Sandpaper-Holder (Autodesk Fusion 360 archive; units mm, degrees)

design "Sandpaper-Holder" references "Base"
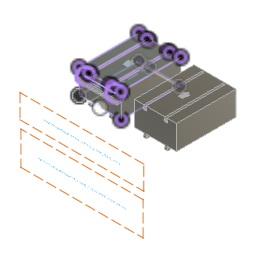
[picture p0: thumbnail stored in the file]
parameter "width" = 110
parameter "depth" = 160
parameter "height" = 50
parameter "wall_thickness" = 2
sketch "Sketch1" plane through (0, 0, 0) normal (0, 1, 0) x axis (1, 0, 0)
  line L1 (110, 0) -> (0, 0)
  line L2 (0, -50) -> (0, 0)
  line L3 (110, -50) -> (0, -50)
  line L4 (110, 0) -> (110, -50)
  line L5 (112, 2) -> (-2, 2)
  line L6 (112, 2) -> (112, -52)
  line L7 (112, -52) -> (-2, -52)
  line L8 (-2, -52) -> (-2, 2)
  point P1 (0, 0)
  point P2 (0, 0)
  point P4 (0, 0)
  point P3 (110, 0)
  point P5 (0, -50)
  coincident P1 P2
  horizontal L1
  coincident P1 P4
  perpendicular L1 L2
  perpendicular L2 L3
  perpendicular L1 L4
  dimension "d6" distance P2 P3 = 110 (= "width")
  dimension "d7" distance P4 P5 = 50 (= "height")
  dimension "d8" = 2 (= "wall_thickness")
extrude "Extrude1" new body sketch "Sketch1" along normal blind 160 (= "depth") bodies "Box"
sketch "Sketch2" plane through (0, 160, 0) normal (0, 1, 0) x axis (-1, 0, 0)
  line L1 (0, 0) -> (0, 50)
  line L2 (-110, 0) -> (0, 0)
  line L3 (-110, 50) -> (-110, 0)
  line L4 (0, 50) -> (-110, 50)
  line L5 (2, 52) -> (2, -2)
  line L6 (-112, 52) -> (2, 52)
  line L7 (-112, -2) -> (-112, 52)
  line L8 (2, -2) -> (-112, -2)
  line L9 (2, 52) -> (2, -2)
  line L10 (-112, 52) -> (2, 52)
  line L11 (-112, -2) -> (-112, 52)
  line L12 (2, -2) -> (-112, -2)
  line L13 (2, 52) -> (-112, 52)
  line L14 (2, -2) -> (2, 52)
  line L15 (-112, -2) -> (2, -2)
  line L16 (-112, 52) -> (-112, -2)
  point P6 (2, -2)
  point P16 (2, -2)
  point P8 (-112, 52)
  point P14 (-112, 52)
  horizontal L13
  vertical L14
  horizontal L15
  vertical L16
  coincident P6 P16
  coincident P8 P14
extrude "Extrude2" add sketch "Sketch2" along normal blind 2 (= "wall_thickness")
fillet "Fillet1" radius 1 (= "wall_thickness / 2")
component_insert "Component Insert"
sketch "Sketch3" plane through (0, 55.6118, 0) normal (0, 1, 0) x axis (-1, 0, 0)
  line L1 (0, 52.6059) -> (-80, 52.6059)
  line L2 (0, 60) -> (0, 52.6059)
  line L3 (-80, 60) -> (0, 60)
  line L4 (-80, 52.6059) -> (-80, 60)
  line L5 (-80, 60) -> (0, 60)
move "Move1"
move "Move2"
extrude "Extrude3" new body of existing geometry blind 410
extrude "Extrude4" new body of existing geometry blind 97 bodies "Slider Back"
remove_body "RemoveBody1"
extrude "Extrude6" add of existing geometry to an object
sketch "Sketch4" plane through (0, 0, 6) normal (0, 0, -1) x axis (1, 0, 0)
  line L1 (97, -217.6118) -> (-17, -217.6118)
  line L2 (97, -55.6118) -> (97, -217.6118)
  line L3 (-17, -55.6118) -> (97, -55.6118)
  line L4 (-17, -217.6118) -> (-17, -55.6118)
  line L5 (40, -55.6118) -> (-17, -55.6118)
  line L6 (40, -217.6118) -> (39.5082, -55.6118)
  line L7 (11.5, -217.6118) -> (11.5, -55.6118)
  line L8 (-17, -212.6118) -> (-17, -217.6118)
  line L9 (97, -212.6118) -> (-17, -212.6118)
  point P5 (-17, -55.6118)
  point P6 (-17, -55.6118)
  point P8 (39.5082, -55.6118)
  point P9 (40, -217.6118)
  point P10 (11.5, -55.6118)
  point P11 (11.5, -217.6118)
  point P2 (-17, -217.6118)
  point P12 (-17, -217.6118)
  point P14 (97, -212.6118)
  point P7 (40, -55.6118)
  point P13 (-17, -212.6118)
  coincident P5 P6
  perpendicular L4 L5
  coincident L5 P8
  midpoint L1 P9
  midpoint L5 P10
  coincident L1 P11
  perpendicular L1 L7
  coincident P2 P12
  perpendicular L1 L8
  coincident L2 P14
  perpendicular L2 L9
  dimension "d23" distance P6 P7 = 57 (= "( wall_thickness + wall_thickness + width ) / 2")
  dimension "d24" distance P12 P13 = 5
copy_paste_bodies "CopyPasteBodies1"
move "Move3"
move "Move4"
extrude "Extrude7" add of existing geometry to an object
work_plane "WorkPlane1" AlongDistance -57 (= "-( wall_thickness + wall_thickness + width ) / 2")
mirror "Mirror1" mirrorStitchTolerance 0.1 bodies "Slider (1) (1)"
extrude "Extrude8" add of existing geometry blind 12
sketch "Sketch5" plane through (160, 0, 0) normal (1, 0, 0) x axis (0, 1, 0)
  line L1 (44.6118, 54.0559) -> (44.6118, 50.6559)
  line L2 (49.1118, 54.0559) -> (44.6118, 54.0559)
  line L3 (49.1118, 52.6059) -> (49.1118, 54.0559)
  line L4 (55.6118, 52.6059) -> (49.1118, 52.6059)
  line L5 (55.6118, 60) -> (55.6118, 52.6059)
  line L6 (39.6118, 60) -> (55.6118, 60)
  line L7 (39.6118, -40) -> (39.6118, 60)
  line L8 (55.6118, -40) -> (39.6118, -40)
  line L9 (55.6118, 47.0059) -> (55.6118, -40)
  line L10 (49.1118, 47.0059) -> (55.6118, 47.0059)
  line L11 (49.1118, 45.5559) -> (49.1118, 47.0059)
  line L12 (44.6118, 45.5559) -> (49.1118, 45.5559)
  line L13 (44.6118, 48.9559) -> (44.6118, 45.5559)
  line L14 (44.6118, 54.0559) -> (44.6118, 50.6559)
  line L15 (49.1118, 54.0559) -> (44.6118, 54.0559)
  line L16 (49.1118, 52.6059) -> (49.1118, 54.0559)
  line L17 (55.6118, 52.6059) -> (49.1118, 52.6059)
  line L18 (44.6118, 48.9559) -> (44.6118, 45.5559)
  line L19 (44.6118, 45.5559) -> (49.1118, 45.5559)
  line L20 (49.1118, 45.5559) -> (49.1118, 47.0059)
  line L21 (49.1118, 47.0059) -> (55.6118, 47.0059)
  line L22 (55.6118, 47.0059) -> (55.6118, 52.6059)
  arc A1 centre (44.6118, 49.8059) radius 0.85 clockwise from (44.6118, 48.9559) to (44.6118, 50.6559)
  arc A2 centre (44.6118, 49.8059) radius 0.85 clockwise from (44.6118, 48.9559) to (44.6118, 50.6559)
  point P24 (55.6118, 52.6059)
  point P36 (55.6118, 52.6059)
  point P34 (55.6118, 47.0059)
  point P37 (55.6118, 47.0059)
  coincident P24 P36
  coincident P34 P37
sketch "Sketch6" plane through (0, 0, 72) normal (0, 0, 1) x axis (-1, 0, 0)
  line L1 (17, -217.6118) -> (-97, -217.6118)
  line L2 (17, -55.6118) -> (17, -217.6118)
  line L3 (-97, -55.6118) -> (17, -55.6118)
  line L4 (-97, -217.6118) -> (-97, -55.6118)
  line L5 (-11.5, -217.6118) -> (-11.5, -55.6118)
extrude "Extrude9" new body sketch "Sketch5" profile of L1 L2 L3 L4 L10 L11 L12 L13 A1 L14 L15 L16 L17 A2 L18 L19 L20 L21 L22 along normal blind 20 bodies "Hole"
move "Move5"
move "Move6"
extrude "Extrude10" add of existing geometry to an object
extrude "Extrude11" add of existing geometry blind 1
mirror "Mirror2" mirrorStitchTolerance 0.1 bodies "Hole (1)"
split "Split1" bodies "Box (1)", "Box (2)"
remove_body "RemoveBody2"
remove_body "RemoveBody3"
remove_body "RemoveBody4"
remove_body "RemoveBody5"
combine "Combine1" bodies "Slider (1) (1)", "Box (2)"
sketch "Text" plane through (0, 0, 72) normal (0, 0, 1) x axis (-1, 0, 0)
  line L1 (-14.3, -55.6118) -> (-14.3, -213.6118)
  line L2 (-65.7, -55.6118) -> (-14.3, -55.6118)
  line L3 (-65.7, -213.6118) -> (-65.7, -55.6118)
  line L4 (-71.3, -213.6118) -> (-65.7, -213.6118)
  line L5 (-71.3, -55.6118) -> (-71.3, -213.6118)
  line L6 (-97, -55.6118) -> (-71.3, -55.6118)
  line L7 (-97, -217.6118) -> (-97, -55.6118)
  line L8 (17, -217.6118) -> (-97, -217.6118)
  line L9 (17, -55.6118) -> (17, -217.6118)
  line L10 (-8.7, -55.6118) -> (17, -55.6118)
  line L11 (-8.7, -213.6118) -> (-8.7, -55.6118)
  line L12 (-14.3, -213.6118) -> (-8.7, -213.6118)
  curve K1
  curve K2
  curve K3
  curve K4
  point P4 (-65.7, -55.6118)
  point P2 (-14.3, -213.6118)
  coincident P4
  coincident P2
  dimension "d40" Text1-Height = 3
extrude "Extrude12" cut sketch "Text" against normal blind 2
sketch "Filename" plane through (0, 0, 0) normal (0, 1, 0) x axis (1, 0, 0)
  dimension "d43" = 5
  dimension "d44" = 5
copy_paste_bodies "CopyPasteBodies2"
move "Move7"
combine "Combine2" bodies "Box"
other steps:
base_feature "Base Feature1" bodies "Slider", "Box"
base_feature "Base Feature2" bodies "Box", "Box (1)"
named bodies: "Box", "Slider Back", "Slider", "Slider (1) (1)", "Hole", "Hole (1)", "Box (1)", "Box (2)"

design "Base"
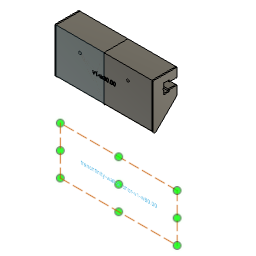
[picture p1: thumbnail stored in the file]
parameter "wall_anchor_height" = 60
parameter "wall_anchor_width" = 20
parameter "wall_anchor_angle" = 45
parameter "width_per_slot" = 40
parameter "slot_inner_width" = 8.5
parameter "slot_inner_height" = 4.5
parameter "slot_outer_width" = 5.6
parameter "slot_outer_height" = 6.5
parameter "slot_dept" = 15
parameter "print_tolerance" = 0.12
parameter "base_plate_thickness" = 16
parameter "base_plate_slot_height" = 50
parameter "wall_anchor_angle_rounded_border" = 1.5
parameter "base_plate_screw_hole_diameter" = 4
parameter "base_plate_screw_head_diameter" = 8
parameter "base_plate_screw_head_height" = 4
parameter "base_plate_screw_hole_side_distance" = 7
parameter "slot_screw_head_width" = 4.42 (= "4.3 mm + print_tolerance")
parameter "slot_screw_thread_width" = 2.12 (= "2 mm + print_tolerance")
parameter "slot_screw_head_height" = 2.12 (= "2 mm + print_tolerance")
parameter "width" = 80
parameter "filament_hole_width" = 1.7
parameter "plate_height" = 80
parameter "screw_plate_screw_head_widht" = 8
parameter "screw_plate_screw_head_height" = 4
parameter "screw_plate_screw_diameter" = 4
parameter "SkadisSlotW_1" = 5 comment "Skadis Slot Width"
parameter "SkadisSlotH_1" = 15 comment "Skadis Slot Height"
parameter "ClearanceHoriz_1" = 0.3 comment "Horizontal clearance for peg"
parameter "ClearanceVerticle_1" = 1 comment "Vertical clearance for peg"
parameter "PegW_1" = 4.7 (= "SkadisSlotW_1 - ClearanceHoriz_1") comment "Calculated Peg Width"
parameter "PegH_1" = 14 (= "SkadisSlotH_1 - ClearanceVerticle_1") comment "Calculated Peg Height"
parameter "PegD_1" = 5.2 (= "5 mm + 0.2 mm")
parameter "SkadisSlotW_2" = 5 comment "Skadis Slot Width"
parameter "SkadisSlotH_2" = 15 comment "Skadis Slot Height"
parameter "ClearanceHoriz_2" = 0.3 comment "Horizontal clearance for peg"
parameter "ClearanceVerticle_2" = 1 comment "Vertical clearance for peg"
parameter "PegW_2" = 4.7 (= "SkadisSlotW_2 - ClearanceHoriz_2") comment "Calculated Peg Width"
parameter "PegH_2" = 14 (= "SkadisSlotH_2 - ClearanceVerticle_2") comment "Calculated Peg Height"
parameter "PegD_2" = 5.2 (= "5 mm + 0.2 mm")
parameter "SkadisSlotW_3" = 5 comment "Skadis Slot Width"
parameter "SkadisSlotH_3" = 15 comment "Skadis Slot Height"
parameter "ClearanceHoriz_3" = 0.3 comment "Horizontal clearance for peg"
parameter "ClearanceVerticle_3" = 1 comment "Vertical clearance for peg"
parameter "PegW_3" = 4.7 (= "SkadisSlotW_3 - ClearanceHoriz_3") comment "Calculated Peg Width"
parameter "PegH_3" = 14 (= "SkadisSlotH_3 - ClearanceVerticle_3") comment "Calculated Peg Height"
parameter "PegD_3" = 5.2 (= "5 mm + 0.2 mm")
sketch "Side" plane through (0, 0, 0) normal (1, 0, 0) x axis (0, 1, 0)
  line L1 (39.6118, 0) -> (19.6118, 0)
  line L2 (39.6118, 60) -> (39.6118, 0)
  line L3 (19.6118, 60) -> (39.6118, 60)
  line L4 (19.6118, 0) -> (19.6118, 60)
  line L5 (39.6118, 39.6118) -> (0, 0)
  line L6 (56.0196, 0) -> (0, 0)
  point P1 (0, 0)
  point P6 (0, 0)
  point P7 (39.6118, 39.6118)
  point P2 (19.6118, 0)
  point P3 (39.6118, 0)
  point P5 (19.6118, 60)
  horizontal L1
  vertical L2
  horizontal L3
  vertical L4
  horizontal L6
  coincident P1 P6
  coincident L2 P7
  dimension "d4" distance P2 P3 = 20 (= "wall_anchor_width")
  dimension "d5" distance P2 P5 = 60 (= "wall_anchor_height")
  dimension "d6" angle L5 L6 = 45 (= "wall_anchor_angle")
extrude "Extrude1" new body sketch "Side" profile of L1 L2 L3 L4 L5 along normal blind 40 (= "width_per_slot")
sketch "Slot LeftToRight" plane through (0, 0, 0) normal (-1, 0, 0) x axis (0, -1, 0)
  line L1 (-19.6118, 60) -> (-19.6118, 19.6118)
  line L2 (-39.6118, 60) -> (-19.6118, 60)
  line L3 (-39.6118, 39.6118) -> (-39.6118, 60)
  line L4 (-19.6118, 19.6118) -> (-39.6118, 39.6118)
  line L5 (-39.6118, 52.6059) -> (-39.6118, 49.8059)
  line L6 (-39.6118, 47.0059) -> (-39.6118, 49.8059)
  line L7 (-33.1118, 52.6059) -> (-39.6118, 52.6059)
  line L8 (-28.6118, 49.8059) -> (-39.6118, 49.8059)
  line L9 (-28.6118, 54.0559) -> (-28.6118, 49.8059)
  line L10 (-33.1118, 54.0559) -> (-28.6118, 54.0559)
  line L11 (-33.1118, 52.6059) -> (-33.1118, 54.0559)
  line L12 (-28.6118, 45.5559) -> (-28.6118, 49.8059)
  line L13 (-33.1118, 45.5559) -> (-28.6118, 45.5559)
  line L14 (-33.1118, 47.0059) -> (-33.1118, 45.5559)
  line L15 (-33.1118, 47.0059) -> (-39.6118, 47.0059)
  point P6 (-39.6118, 49.8059)
  point P7 (-39.6118, 52.6059)
  point P17 (-39.6118, 47.0059)
  point P9 (-33.1118, 52.6059)
  point P16 (-33.1118, 47.0059)
  point P10 (-28.6118, 49.8059)
  point P13 (-28.6118, 49.8059)
  point P11 (-28.6118, 54.0559)
  point P14 (-28.6118, 45.5559)
  point P12 (-33.1118, 54.0559)
  point P15 (-33.1118, 45.5559)
  midpoint L3 P6
  parallel L3 L5
  parallel L3 L6
  perpendicular L3 L7
  perpendicular L6 L8
  perpendicular L8 L9
  perpendicular L9 L10
  symmetric P7 L8 P17
  symmetric P9 L8 P16
  symmetric P10 L8 P13
  symmetric L8 P11 P14
  symmetric L8 P12 P15
  dimension "d80" distance P6 P7 = 2.8 (= "slot_outer_width / 2")
  dimension "d82" distance P7 P9 = 6.5 (= "slot_outer_height")
  dimension "d84" distance P6 P10 = 11 (= "slot_outer_height + slot_inner_height")
  dimension "d85" distance P10 P11 = 4.25 (= "slot_inner_width / 2")
  dimension "d86" distance P11 P12 = 4.5 (= "slot_inner_height")
extrude "Extrude3" cut sketch "Slot LeftToRight" profile of L3 L5 L6 L7 L9 L10 L11 L12 L13 L14 L15 against normal blind 40 (magnitude of "width_per_slot * -1")
sketch "Plate" plane through (0, 39.6118, 0) normal (0, 1, 0) x axis (-1, 0, 0)
  line L1 (0, 39.6118) -> (-40, 39.6118)
  line L2 (-40, 60) -> (0, 60)
  line L3 (0, 10) -> (0, 60)
  line L4 (-40, 10) -> (-40, 60)
  line L5 (-40, 10) -> (0, 10)
  line L6 (-40, 47.0059) -> (0, 47.0059)
  line L7 (-40, 52.6059) -> (-40, 60)
  line L8 (0, 60) -> (0, 52.6059)
  line L9 (0, 52.6059) -> (-40, 52.6059)
  line L10 (-40, 60) -> (0, 60)
  line L11 (-40, 39.6118) -> (-40, 47.0059)
  line L12 (0, 47.0059) -> (0, 39.6118)
  point P2 (0, 60)
  point P3 (-40, 60)
  point P4 (0, 10)
  point P5 (-40, 10)
  perpendicular L1 L3
  perpendicular L1 L4
  dimension "d36" distance P2 P3 = 40 (= "width_per_slot")
  dimension "d37" distance P2 P4 = 50 (= "base_plate_slot_height")
  dimension "d39" distance P3 P5 = 50 (= "base_plate_slot_height")
extrude "Extrude6" new body sketch "Plate" profile of L1 L2 L3 L4 L5 L6 L7 L8 L9 L10 along normal blind 16 (= "base_plate_thickness") bodies "Base plate with slot"
sketch "Slot" plane through (0, 0, 0) normal (-1, 0, 0) x axis (0, -1, 0)
  line L1 (-19.6118, 60) -> (-19.6118, 19.6118)
  line L2 (-39.6118, 60) -> (-19.6118, 60)
  line L3 (-39.6118, 52.6059) -> (-39.6118, 60)
  line L4 (-33.1118, 52.6059) -> (-39.6118, 52.6059)
  line L5 (-33.1118, 54.0559) -> (-33.1118, 52.6059)
  line L6 (-28.6118, 54.0559) -> (-33.1118, 54.0559)
  line L7 (-28.6118, 45.5559) -> (-28.6118, 54.0559)
  line L8 (-33.1118, 45.5559) -> (-28.6118, 45.5559)
  line L9 (-33.1118, 47.0059) -> (-33.1118, 45.5559)
  line L10 (-39.6118, 47.0059) -> (-33.1118, 47.0059)
  line L11 (-39.6118, 39.6118) -> (-39.6118, 47.0059)
  line L12 (-19.6118, 19.6118) -> (-39.6118, 39.6118)
  line L13 (-33.1118, 52.6059) -> (-39.6118, 52.6059)
  line L14 (-33.1118, 54.0559) -> (-33.1118, 52.6059)
  line L15 (-28.6118, 54.0559) -> (-33.1118, 54.0559)
  line L16 (-28.6118, 45.5559) -> (-28.6118, 54.0559)
  line L17 (-33.1118, 45.5559) -> (-28.6118, 45.5559)
  line L18 (-33.1118, 47.0059) -> (-33.1118, 45.5559)
  line L19 (-39.6118, 47.0059) -> (-33.1118, 47.0059)
  line L20 (-39.6118, 10) -> (-39.6118, 60)
  line L21 (-32.9918, 52.4859) -> (-39.6118, 52.4859)
  line L22 (-32.9918, 53.9359) -> (-32.9918, 52.4859)
  line L23 (-28.7318, 53.9359) -> (-32.9918, 53.9359)
  line L24 (-28.7318, 45.6759) -> (-28.7318, 53.9359)
  line L25 (-32.9918, 45.6759) -> (-28.7318, 45.6759)
  line L26 (-32.9918, 47.1259) -> (-32.9918, 45.6759)
  line L27 (-39.6118, 47.1259) -> (-32.9918, 47.1259)
  line L28 (-33.1118, 52.6059) -> (-39.6118, 52.6059)
  line L29 (-33.1118, 52.6059) -> (-33.1118, 54.0559)
  line L30 (-28.6118, 54.0559) -> (-33.1118, 54.0559)
  line L31 (-28.6118, 45.5559) -> (-28.6118, 54.0559)
  line L32 (-33.1118, 45.5559) -> (-28.6118, 45.5559)
  line L33 (-33.1118, 47.0059) -> (-33.1118, 45.5559)
  line L34 (-39.6118, 47.0059) -> (-33.1118, 47.0059)
  line L35 (-39.6118, 47.0059) -> (-39.6118, 52.6059)
  line L36 (-49.1118, 52.6059) -> (-55.6118, 52.6059)
  line L37 (-49.1118, 52.6059) -> (-49.1118, 54.0559)
  line L38 (-44.6118, 54.0559) -> (-49.1118, 54.0559)
  line L39 (-44.6118, 45.5559) -> (-44.6118, 54.0559)
  line L40 (-49.1118, 45.5559) -> (-44.6118, 45.5559)
  line L41 (-49.1118, 47.0059) -> (-49.1118, 45.5559)
  line L42 (-55.6118, 47.0059) -> (-49.1118, 47.0059)
  line L43 (-55.6118, 47.0059) -> (-55.6118, 52.6059)
  point P15 (-39.6118, 52.6059)
  point P33 (-39.6118, 52.6059)
  point P16 (-33.1118, 52.6059)
  point P34 (-33.1118, 52.6059)
  point P17 (-33.1118, 54.0559)
  point P35 (-33.1118, 54.0559)
  point P36 (-33.1118, 52.6059)
  point P18 (-28.6118, 54.0559)
  point P37 (-28.6118, 54.0559)
  point P19 (-28.6118, 45.5559)
  point P38 (-28.6118, 45.5559)
  point P10 (-28.6118, 45.5559)
  point P39 (-28.6118, 45.5559)
  point P11 (-33.1118, 45.5559)
  point P40 (-33.1118, 45.5559)
  point P41 (-33.1118, 45.5559)
  point P12 (-33.1118, 47.0059)
  point P42 (-33.1118, 47.0059)
  point P21 (-33.1118, 47.0059)
  point P43 (-33.1118, 47.0059)
  point P22 (-39.6118, 47.0059)
  point P44 (-39.6118, 47.0059)
  point P45 (-39.6118, 52.6059)
  point P46 (-39.6118, 47.0059)
  coincident P15 P33
  coincident P16 P34
  coincident P17 P35
  coincident P16 P36
  coincident P18 P37
  coincident P19 P38
  coincident P10 P39
  coincident P11 P40
  coincident P11 P41
  coincident P12 P42
  coincident P21 P43
  coincident P22 P44
  coincident P15 P45
  coincident P22 P46
  dimension "d91" = 0.12 (= "print_tolerance")
  dimension "d96" R-Pattern1-uDistance = -16 (= "base_plate_thickness * -1")
  dimension "d97" R-Pattern1-vDistance = 0
extrude "Extrude7" add sketch "Slot" profile of L20 L24 L23 L27 L22 L25 L26 L21 against normal blind 40 (magnitude of "width_per_slot * -1")
extrude "Extrude8" cut sketch "Slot" profile of L36 L37 L38 L39 L40 L41 L42 L43 no distance stored
sketch "Sketch3" plane through (0, 0, 0) normal (-1, 0, 0) x axis (0, -1, 0)
  line L1 (-32.9918, 47.1259) -> (-39.6118, 47.1259)
  line L2 (-32.9918, 45.6759) -> (-32.9918, 47.1259)
  line L3 (-28.7318, 45.6759) -> (-32.9918, 45.6759)
  line L4 (-28.7318, 53.9359) -> (-28.7318, 45.6759)
  line L5 (-32.9918, 53.9359) -> (-28.7318, 53.9359)
  line L6 (-32.9918, 52.4859) -> (-32.9918, 53.9359)
  line L7 (-39.6118, 52.4859) -> (-32.9918, 52.4859)
  line L8 (-44.6118, 45.5559) -> (-44.6118, 54.0559)
  line L9 (-32.9918, 52.4859) -> (-39.6118, 52.4859)
  line L10 (-32.9918, 53.9359) -> (-32.9918, 52.4859)
  line L11 (-28.7318, 53.9359) -> (-32.9918, 53.9359)
  line L12 (-28.7318, 45.6759) -> (-28.7318, 53.9359)
  line L13 (-32.9918, 45.6759) -> (-28.7318, 45.6759)
  line L14 (-32.9918, 47.1259) -> (-32.9918, 45.6759)
  line L15 (-39.6118, 47.1259) -> (-32.9918, 47.1259)
  line L16 (-39.6118, 47.1259) -> (-39.6118, 52.4859)
  line L17 (-55.6118, 52.4859) -> (-48.9918, 52.4859)
  line L18 (-48.9918, 52.4859) -> (-48.9918, 53.9359)
  line L19 (-48.9918, 53.9359) -> (-44.7318, 53.9359)
  line L20 (-44.7318, 45.6759) -> (-44.7318, 53.9359)
  line L21 (-48.9918, 45.6759) -> (-44.7318, 45.6759)
  line L22 (-48.9918, 47.1259) -> (-48.9918, 45.6759)
  line L23 (-55.6118, 47.1259) -> (-48.9918, 47.1259)
  line L24 (-55.6118, 47.1259) -> (-55.6118, 52.4859)
  line L25 (-55.6118, 47.0059) -> (-49.1118, 47.0059)
  line L26 (-55.6118, 10) -> (-55.6118, 47.0059)
  line L27 (-39.6118, 10) -> (-55.6118, 10)
  line L28 (-39.6118, 47.1259) -> (-39.6118, 10)
  line L29 (-39.6118, 60) -> (-39.6118, 52.4859)
  line L30 (-55.6118, 60) -> (-39.6118, 60)
  line L31 (-55.6118, 52.6059) -> (-55.6118, 60)
  line L32 (-49.1118, 52.6059) -> (-55.6118, 52.6059)
  line L33 (-49.1118, 54.0559) -> (-49.1118, 52.6059)
  line L34 (-44.6118, 54.0559) -> (-49.1118, 54.0559)
  line L35 (-49.1118, 45.5559) -> (-44.6118, 45.5559)
  line L36 (-49.1118, 47.0059) -> (-49.1118, 45.5559)
  point P9 (-39.6118, 52.4859)
  point P20 (-39.6118, 52.4859)
  point P19 (-39.6118, 47.1259)
  point P21 (-39.6118, 47.1259)
  coincident P9 P20
  coincident P19 P21
  dimension "d105" R-Pattern1-vDistance = 0
extrude "Extrude3" new body sketch "Sketch3" profile of L17 L18 L19 L20 L21 L22 L23 L24 against normal blind 40 (magnitude of "width_per_slot * -1")
sketch "Screw hole" plane through (0, 28.6118, 0) normal (0, 1, 0) x axis (-1, 0, 0)
  line L1 (0, 54.0559) -> (0, 45.5559)
  line L2 (-40, 54.0559) -> (0, 54.0559)
  line L3 (-40, 45.5559) -> (-40, 54.0559)
  line L4 (0, 45.5559) -> (-40, 45.5559)
  line L5 (0, 45.5559) -> (-40, 54.0559)
  line L6 (-40, 45.5559) -> (0, 54.0559)
  circle C1 centre (-20, 49.8059) radius 2.21
  circle C2 centre (-20, 49.8059) radius 1.06
  point P4 (-40, 54.0559)
  point P6 (-40, 54.0559)
  point P2 (0, 45.5559)
  point P7 (0, 45.5559)
  point P3 (0, 54.0559)
  point P8 (0, 54.0559)
  point P5 (-40, 45.5559)
  point P9 (-40, 45.5559)
  point P10 (-20, 49.8059)
  coincident P4 P6
  coincident P2 P7
  coincident P3 P8
  coincident P5 P9
  midpoint L5 P10
  concentric C1 C2
  dimension "d119" diameter C1 = 4.42 (= "slot_screw_head_width")
  dimension "d120" diameter C2 = 2.12 (= "slot_screw_thread_width")
extrude "Extrude4" cut sketch "Screw hole" profile of C2 against normal blind 2000
extrude "Extrude5" cut sketch "Screw hole" profile of C1 C2 no distance stored
fillet "Fillet1" radius 1.5 (= "wall_anchor_angle_rounded_border")
work_plane "WorkPlane1" sketch "Slot LeftToRight" AlongDistance -20 (= "-width_per_slot / 2")
sketch "Screw head" plane through (20, 0, 0) normal (-1, 0, 0) x axis (0, -1, 0)
  line L1 (-28.6118, 52.0159) -> (-28.6118, 47.5959)
  line L2 (-26.4918, 52.0159) -> (-26.4918, 47.5959)
  line L3 (-26.4918, 48.7459) -> (-26.4918, 50.8659)
  line L4 (-26.4918, 50.8659) -> (-28.6118, 52.0159)
  line L5 (-26.4918, 52.0159) -> (-28.6118, 52.0159)
  point P3 (-28.6118, 52.0159)
  point P8 (-28.6118, 52.0159)
  point P6 (-26.4918, 50.8659)
  point P9 (-26.4918, 50.8659)
  point P10 (-28.6118, 52.0159)
  point P5 (-26.4918, 52.0159)
  point P11 (-26.4918, 52.0159)
  coincident P3 P8
  coincident P6 P9
  coincident P3 P10
  coincident P5 P11
revolve "Revolve1" sketch "Screw head" AlongAngle 360
rectangular_pattern "R-Pattern2" countU 2 (= "floor(( width / mm ) / ( width_per_slot / cm * 10 ))") uSpaceDistance 40 (= "width_per_slot") vSpaceDistance 0 bodies "Wall anchor part (1)"
work_plane "WorkPlane2"
extrude "Extrude12" new body of existing geometry no distance stored
mirror "Mirror3" mirrorStitchTolerance 0.1
sketch "filename" plane through (0, 19.6118, 0) normal (0, -1, 0) x axis (1, 0, 0)
  dimension "d216" = 3
sketch "Text" plane through (0, 19.6118, 0) normal (0, -1, 0) x axis (1, 0, 0)
  line L1 (81, 60) -> (81, 23.2332)
  line L2 (80, 23.2332) -> (80, 60)
  line L3 (81, 23.2332) -> (80, 23.2332)
  line L4 (81, 60) -> (81, 23.2332)
  line L5 (80, 60) -> (81, 60)
  line L6 (0, 60) -> (0, 23.2332)
  line L7 (-1, 60) -> (0, 60)
  line L8 (-1, 23.2332) -> (-1, 60)
  line L9 (0, 23.2332) -> (-1, 23.2332)
  curve K1
  curve K2
  curve K3
  curve K4
  line L10 (80, 60) -> (40, 60)
  point P4 (81, 23.2332)
  point P2 (-1, 60)
  coincident P4
  coincident P2
  parallel K3 L10
  dimension "d229" Text1-Height = 3
extrude "Extrude19" cut sketch "Text" against normal blind 2
extrude "Extrude14" cut of existing geometry blind 20 (= "( width_per_slot - width ) / -2")
extrude "Extrude15" cut of existing geometry blind 20 (= "( width_per_slot - width ) / -2")
extrude "Extrude9" cut of existing geometry blind -39 (= "-width_per_slot + 1 mm")
extrude "Extrude10" add of existing geometry blind 79 (= "width - 1 mm")
extrude "Extrude13" cut of existing geometry blind -30
extrude "Extrude14" add of existing geometry blind 80 (= "plate_height")
sketch "Sketch7" plane through (0, 39.6118, 0) normal (0, -1, 0) x axis (1, 0, 0)
  dimension "d236" = 3
extrude "Extrude11" cut sketch "Sketch7" against normal blind 2
sketch "File name" plane through (0, 39.6118, 0) normal (0, -1, 0) x axis (1, 0, 0)
  line L1 (0, 47.1259) -> (80, 47.1259)
  line L2 (0, -40) -> (0, 47.1259)
  line L3 (80, 47.1259) -> (80, -40)
  curve K1
  curve K2
  curve K3
  curve K4
  line L4 (80, -40) -> (0, -40)
  curve K5 (33.1436, -0.053) -> (33.383, -0.2495)
  curve K6 (37.9014, 1.3488) -> (37.4778, 1.0786)
  curve K7 (39.162, 1.0582) -> (38.7425, 1.3488)
  curve K8 (39.3073, 0.5793) -> (39.162, 1.0582)
  curve K9 (39.0351, -0.0673) -> (39.3073, 0.5793)
  curve K10 (38.3189, -0.3293) -> (39.0351, -0.0673)
  curve K11 (37.6027, -0.0673) -> (38.3189, -0.3293)
  curve K12 (37.3305, 0.5896) -> (37.6027, -0.0673)
  curve K13 (37.4778, 1.0786) -> (37.3305, 0.5896)
  curve K14 (47.014, -0.1533) -> (47.3394, 0.3481)
  curve K15 (46.4696, -0.3293) -> (47.014, -0.1533)
  curve K16 (45.7882, -0.0182) -> (46.4696, -0.3293)
  curve K17 (45.4915, 1.2014) -> (45.7882, -0.0182)
  curve K18 (33.383, -0.2495) -> (33.7145, -0.3272)
  curve K19 (44.6832, -0.1533) -> (45.0085, 0.3481)
  curve K20 (44.1388, -0.3293) -> (44.6832, -0.1533)
  curve K21 (43.4574, -0.0182) -> (44.1388, -0.3293)
  curve K22 (43.1606, 1.2014) -> (43.4574, -0.0182)
  curve K23 (41.1879, -0.1533) -> (41.5133, 0.3481)
  curve K24 (40.6436, -0.3293) -> (41.1879, -0.1533)
  curve K25 (39.9621, -0.0182) -> (40.6436, -0.3293)
  curve K26 (39.6654, 1.2014) -> (39.9621, -0.0182)
  curve K27 (49.1074, 4.5289) -> (49.4328, 5.0302)
  curve K28 (48.5631, 4.3529) -> (49.1074, 4.5289)
  curve K29 (47.8817, 4.6639) -> (48.5631, 4.3529)
  curve K30 (47.5849, 5.8836) -> (47.8817, 4.6639)
  curve K31 (46.7766, 4.5289) -> (47.102, 5.0302)
  curve K32 (46.2323, 4.3529) -> (46.7766, 4.5289)
  curve K33 (45.5508, 4.6639) -> (46.2323, 4.3529)
  curve K34 (45.2541, 5.8836) -> (45.5508, 4.6639)
  curve K35 (47.4478, 1.2014) -> (47.3803, 1.9095)
  curve K36 (47.3394, 0.3481) -> (47.4478, 1.2014)
  curve K37 (49.5413, 5.8836) -> (49.4737, 6.5916)
  curve K38 (49.4328, 5.0302) -> (49.5413, 5.8836)
  curve K39 (41.6218, 1.2014) -> (41.5542, 1.9095)
  curve K40 (41.5133, 0.3481) -> (41.6218, 1.2014)
  curve K41 (45.117, 1.2014) -> (45.0495, 1.9095)
  curve K42 (45.0085, 0.3481) -> (45.117, 1.2014)
  curve K43 (34.1934, -0.186) -> (34.5413, 0.2233)
  curve K44 (33.7145, -0.3272) -> (34.1934, -0.186)
  curve K45 (47.2104, 5.8836) -> (47.1429, 6.5916)
  curve K46 (47.102, 5.0302) -> (47.2104, 5.8836)
  curve K47 (47.1941, 2.3556) -> (46.8933, 2.6359)
  curve K48 (47.3803, 1.9095) -> (47.1941, 2.3556)
  curve K49 (34.662, 0.8249) -> (34.5535, 1.3958)
  curve K50 (34.5413, 0.2233) -> (34.662, 0.8249)
  curve K51 (44.8632, 2.3556) -> (44.5624, 2.6359)
  curve K52 (45.0495, 1.9095) -> (44.8632, 2.3556)
  curve K53 (41.368, 2.3556) -> (41.0672, 2.6359)
  curve K54 (41.5542, 1.9095) -> (41.368, 2.3556)
  curve K55 (49.2875, 7.0377) -> (48.9867, 7.3181)
  curve K56 (49.4737, 6.5916) -> (49.2875, 7.0377)
  curve K57 (46.9567, 7.0377) -> (46.6559, 7.3181)
  curve K58 (47.1429, 6.5916) -> (46.9567, 7.0377)
  line L5 (33.1436, -1.111) -> (33.1436, -0.053)
  line L6 (32.7752, -1.111) -> (33.1436, -1.111)
  dimension "d239" Text1-Height = 3
sketch "Sketch4" plane through (40, 0, 0) normal (1, 0, 0) x axis (0, 1, 0)
  line L1 (44.7318, 53.9359) -> (48.9918, 53.9359)
  line L2 (44.7318, 45.6759) -> (44.7318, 53.9359)
  line L3 (48.9918, 45.6759) -> (44.7318, 45.6759)
  line L4 (48.9918, 47.1259) -> (48.9918, 45.6759)
  line L5 (55.6118, 47.1259) -> (48.9918, 47.1259)
  line L6 (55.6118, 52.4859) -> (55.6118, 47.1259)
  line L7 (48.9918, 52.4859) -> (55.6118, 52.4859)
  line L8 (48.9918, 53.9359) -> (48.9918, 52.4859)
  circle C1 centre (44.7318, 49.8059) radius 0.85
  point P10 (44.7318, 49.8059)
  midpoint L2 P10
  dimension "d241" diameter C1 = 1.7 (= "filament_hole_width")
extrude "Extrude4" cut sketch "Sketch4" profile of L2 C1 no distance stored
sketch "Sketch15" plane through (-1, 0, 0) normal (-1, 0, 0) x axis (0, -1, 0)
  line L1 (-19.6118, 60) -> (-19.6118, 23.2332)
  line L2 (-39.6118, 60) -> (-19.6118, 60)
  line L3 (-39.6118, 52.6059) -> (-39.6118, 60)
  line L4 (-33.1118, 52.6059) -> (-39.6118, 52.6059)
  line L5 (-33.1118, 54.0559) -> (-33.1118, 52.6059)
  line L6 (-28.6118, 54.0559) -> (-33.1118, 54.0559)
  line L7 (-28.6118, 45.5559) -> (-28.6118, 54.0559)
  line L8 (-33.1118, 45.5559) -> (-28.6118, 45.5559)
  line L9 (-33.1118, 47.0059) -> (-33.1118, 45.5559)
  line L10 (-39.6118, 47.0059) -> (-33.1118, 47.0059)
  line L11 (-39.6118, 39.6118) -> (-39.6118, 47.0059)
  line L12 (-22.1725, 22.1725) -> (-39.6118, 39.6118)
  arc A1 centre (-21.1118, 23.2332) radius 1.5 clockwise from (-19.6118, 23.2332) to (-22.1725, 22.1725)
  circle C1 centre (-28.6118, 49.8059) radius 0.85
  point P16 (-28.6118, 49.8059)
  midpoint L7 P16
  dimension "d244" diameter C1 = 1.7 (= "filament_hole_width")
sketch "Sketch9" plane through (80, 0, 0) normal (1, 0, 0) x axis (0, 1, 0)
  line L1 (49.1118, 47.0059) -> (55.6118, 47.0059)
  line L2 (49.1118, 45.5559) -> (49.1118, 47.0059)
  line L3 (44.6118, 45.5559) -> (49.1118, 45.5559)
  line L4 (44.6118, 54.0559) -> (44.6118, 45.5559)
  line L5 (49.1118, 54.0559) -> (44.6118, 54.0559)
  line L6 (49.1118, 52.6059) -> (49.1118, 54.0559)
  line L7 (55.6118, 52.6059) -> (49.1118, 52.6059)
  line L8 (55.6118, 47.0059) -> (55.6118, -40)
  line L9 (39.6118, 60) -> (55.6118, 60)
  line L10 (39.6118, 52.4859) -> (39.6118, 60)
  line L11 (32.9918, 52.4859) -> (39.6118, 52.4859)
  line L12 (32.9918, 53.9359) -> (32.9918, 52.4859)
  line L13 (28.7318, 53.9359) -> (32.9918, 53.9359)
  line L14 (28.7318, 45.6759) -> (28.7318, 53.9359)
  line L15 (32.9918, 45.6759) -> (28.7318, 45.6759)
  line L16 (32.9918, 47.1259) -> (32.9918, 45.6759)
  line L17 (39.6118, 47.1259) -> (32.9918, 47.1259)
  line L18 (55.6118, 60) -> (55.6118, 52.6059)
  line L19 (39.6118, -40) -> (39.6118, 47.1259)
  line L20 (55.6118, -40) -> (39.6118, -40)
  circle C1 centre (28.7318, 49.8059) radius 0.85
  circle C2 centre (44.6118, 49.8059) radius 0.85
  point P20 (28.7318, 49.8059)
  point P21 (44.6118, 49.8059)
  midpoint L14 P20
  midpoint L4 P21
  dimension "d247" diameter C1 = 1.7 (= "filament_hole_width")
  dimension "d250" diameter C2 = 1.7 (= "filament_hole_width")
extrude "Extrude12" cut sketch "Sketch9" profile of L4 L14 C1 C2 no distance stored
sketch "Sketch16" plane through (0, 19.6118, 0) normal (0, -1, 0) x axis (1, 0, 0)
  dimension "d253" = 3
extrude "Extrude22" cut sketch "Sketch16" against normal blind 2
extrude "Extrude23" cut sketch "Sketch15" profile of L7 C1 against normal blind 260 and along normal blind 80
sketch "Sketch17" plane through (0, 19.6118, 0) normal (0, -1, 0) x axis (1, 0, 0)
  dimension "d258" = 3
extrude "Extrude24" cut sketch "Sketch17" against normal blind 2
extrude "Extrude26" cut sketch "Text" against normal blind 2
extrude "Extrude27" cut sketch "Text" against normal blind 2
sketch "Sketch1" plane through (80, 0, 0) normal (1, 0, 0) x axis (0, 1, 0)
  line L1 (28.7318, 45.6759) -> (28.7318, 48.9559)
  line L2 (32.9918, 45.6759) -> (28.7318, 45.6759)
  line L3 (32.9918, 47.1259) -> (32.9918, 45.6759)
  line L4 (39.6118, 47.1259) -> (32.9918, 47.1259)
  line L5 (39.6118, -40) -> (39.6118, 47.1259)
  line L6 (55.6118, -40) -> (39.6118, -40)
  line L7 (55.6118, 47.0059) -> (55.6118, -40)
  line L8 (49.1118, 47.0059) -> (55.6118, 47.0059)
  line L9 (49.1118, 45.5559) -> (49.1118, 47.0059)
  line L10 (44.6118, 45.5559) -> (49.1118, 45.5559)
  line L11 (44.6118, 48.9559) -> (44.6118, 45.5559)
  line L12 (44.6118, 54.0559) -> (44.6118, 50.6559)
  line L13 (49.1118, 54.0559) -> (44.6118, 54.0559)
  line L14 (49.1118, 52.6059) -> (49.1118, 54.0559)
  line L15 (55.6118, 52.6059) -> (49.1118, 52.6059)
  line L16 (55.6118, 60) -> (55.6118, 52.6059)
  line L17 (39.6118, 60) -> (55.6118, 60)
  line L18 (39.6118, 52.4859) -> (39.6118, 60)
  line L19 (32.9918, 52.4859) -> (39.6118, 52.4859)
  line L20 (32.9918, 53.9359) -> (32.9918, 52.4859)
  line L21 (28.7318, 53.9359) -> (32.9918, 53.9359)
  line L22 (28.7318, 50.6559) -> (28.7318, 53.9359)
  line L23 (55.6118, 47.0059) -> (55.6118, -40)
  line L24 (39.6118, 47.1259) -> (39.6118, 52.4859)
  arc A1 centre (28.7318, 49.8059) radius 0.85 clockwise from (28.7318, 50.6559) to (28.7318, 48.9559)
  arc A2 centre (44.6118, 49.8059) radius 0.85 clockwise from (44.6118, 48.9559) to (44.6118, 50.6559)
  point P24 (39.6118, 52.4859)
  point P30 (39.6118, 52.4859)
  point P8 (39.6118, 47.1259)
  point P31 (39.6118, 47.1259)
  coincident P24 P30
  coincident P8 P31
extrude "Extrude1" new body sketch "Sketch1" profile of L5 L6 L7 L8 L9 L10 L11 A2 L12 L13 L14 L15 L16 L17 L18 L23 L24 along normal blind 80 (= "width") bodies "Screw plate"
sketch "Screw Base" plane through (0, 55.6118, 0) normal (0, 1, 0) x axis (-1, 0, 0)
  line L1 (-80, 47.0059) -> (-80, -40)
  line L2 (-160, 47.0059) -> (-80, 47.0059)
  line L3 (-160, -40) -> (-160, 47.0059)
  line L4 (-80, -40) -> (-160, -40)
  line L5 (-120, -40) -> (-120, 47.0059)
  line L6 (-120, 35.0059) -> (-120, 47.0059)
  circle C1 centre (-120, 35.0059) radius 4
  circle C2 centre (-120, 35.0059) radius 2
  point P6 (-120, 47.0059)
  point P7 (-120, -40)
  point P8 (-120, 35.0059)
  point P9 (-120, 35.0059)
  midpoint L2 P6
  midpoint L4 P7
  perpendicular L2 L6
  coincident P8 P9
  concentric C1 C2
  dimension "d276" distance P6 P8 = 12
  dimension "d280" diameter C1 = 8 (= "screw_plate_screw_head_widht")
  dimension "d281" diameter C2 = 4 (= "base_plate_screw_hole_diameter")
work_plane "WorkPlane1" sketch "Screw Base" AlongDistance -4 (= "screw_plate_screw_head_height * -1")
sketch "Screw Head" plane through (0, 51.6118, 0) normal (0, 1, 0) x axis (1, 0, 0)
  circle C1 centre (120, -35.0059) radius 2
extrude "Extrude2" new body sketch "Screw Head" to an object bodies "Screw hole"
loft "Loft1" sketch "Screw Head" + "Screw Base"
rectangular_pattern "R-Pattern1" countU 2 (= "floor(width / 30 / mm)") uSpaceDistance 30 vSpaceDistance 62 (= "plate_height - 18 mm") bodies "Screw hole (3)", "Screw hole (1)", "Screw hole (2)", "Screw hole (12)", "Screw hole (4)"
split "Split1" bodies "Screw plate (1)", "Screw plate (3)", "Screw plate (2)", "Screw plate"
sketch "Text" plane through (0, 39.6118, 0) normal (0, -1, 0) x axis (1, 0, 0)
  dimension "d289" = 3
sketch "Filename" plane through (0, 0, 0) normal (0, 1, 0) x axis (1, 0, 0)
  dimension "d290" = 5
extrude "Extrude3" cut sketch "Text" against normal blind 2
sketch "Sketch6" plane through (0, 0, 0) normal (0, 1, 0) x axis (1, 0, 0)
  dimension "d293" = 5
sketch "Sketch1" plane through (204, 0, 0) normal (1, 0, 0) x axis (0, 1, 0)
  line L1 (44.6118, 54.0559) -> (44.6118, 50.6559)
  line L2 (49.1118, 54.0559) -> (44.6118, 54.0559)
  line L3 (49.1118, 52.6059) -> (49.1118, 54.0559)
  line L4 (55.6118, 52.6059) -> (49.1118, 52.6059)
  line L5 (55.6118, 60) -> (55.6118, 52.6059)
  line L6 (39.6118, 60) -> (55.6118, 60)
  line L7 (39.6118, -40) -> (39.6118, 60)
  line L8 (55.6118, -40) -> (39.6118, -40)
  line L9 (55.6118, 47.0059) -> (55.6118, -40)
  line L10 (49.1118, 47.0059) -> (55.6118, 47.0059)
  line L11 (49.1118, 45.5559) -> (49.1118, 47.0059)
  line L12 (44.6118, 45.5559) -> (49.1118, 45.5559)
  line L13 (44.6118, 48.9559) -> (44.6118, 45.5559)
  arc A1 centre (44.6118, 49.8059) radius 0.85 clockwise from (44.6118, 48.9559) to (44.6118, 50.6559)
extrude "Extrude1" new body sketch "Sketch1" along normal blind 80 (= "width")
position "Position1"
sketch "Sketch1" plane through (0, 0, 0) normal (0, 1, 0) x axis (1, 0, 0)
  line L1 (-2.35, 22.35) -> (-2.35, 31.65)
  line L2 (2.35, 31.65) -> (2.35, 22.35)
  line L3 (0, 20) -> (0, 34)
  arc A1 centre (0, 22.35) radius 2.35 clockwise from (2.35, 22.35) to (-2.35, 22.35)
  arc A2 centre (0, 28.85) radius 2.35 clockwise from (2.35, 28.85) to (-2.35, 28.85)
  arc A3 centre (0, 31.65) radius 2.35 clockwise from (-2.35, 31.65) to (2.35, 31.65)
  point P7 (0, 34)
  point P3 (0, 20)
  point P2 (-2.35, 28.85)
  point P10 (2.35, 28.85)
  point P4 (0, 28.85)
  point P6 (0, 31.65)
  point P13 (0, 0)
  point P14 (0, 0)
  tangent L1 A1
  tangent A1 L2
  parallel L1 L2
  tangent A3 L2
  tangent L1 A3
  midpoint P7 A3
  midpoint P3 A1
  vertical L3
  coincident P2 L1
  coincident P10 L2
  coincident P4 L3
  equal A2 A3
  horizontal P2 P10
  vertical P6 P13
  dimension "d333_1" distance P3 P7 = 14 (= "PegH_3")
  dimension "d334_1" distance L1 L2 = 4.7 (= "PegW_3")
  dimension "d336_1" = 7.5 (= "SkadisSlotH_3 / 2")
  dimension "d341_1" distance A1 P14 = 20
extrude "Extrude1" new body sketch "Sketch1" profile of L1 A2 A3 L2 against normal blind 5.2 named "d342_1" (magnitude of "-PegD_3")
extrude "Extrude2" sketch "Sketch1" profile of L1 A1 A2 A3 L2 blind -5.2 (= "-PegD_3") named "d345_1"
sketch "Sketch3" plane through (0, 39.6118, 0) normal (0, -1, 0) x axis (1, 0, 0)
  line L1 (204, -40) -> (204, 60)
  line L2 (306, -40) -> (204, -40)
  line L3 (306, 60) -> (306, -40)
  line L4 (204, 60) -> (306, 60)
  line L5 (306, 50.6559) -> (204, 50.6559)
  line L6 (255, -40) -> (255, 60)
  circle C1 centre (255, 50.6559) radius 6.3441
  point P8 (255, 60)
  point P9 (255, -40)
  point P10 (255, 50.6559)
  midpoint L4 P8
  midpoint L2 P9
  midpoint L5 P10
position "Position2"
move "Move1"
rectangular_pattern "R-Pattern2" countU 2 (= "ceil(width / 40 / mm)") uSpaceDistance 40 vSpaceDistance 0
sketch "Text" plane through (0, 39.6118, 0) normal (0, -1, 0) x axis (1, 0, 0)
  dimension "d309" = 3
extrude "Extrude2" cut sketch "Text" against normal blind 2
sketch "Filename" plane through (0, 0, 0) normal (0, 1, 0) x axis (1, 0, 0)
  dimension "d312" = 3
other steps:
create_component "CreateComponent1"
create_component "CreateComponent2"
create_component "CreateComponent3"
create_component "CreateComponent5"
create_component "CreateComponent6"
create_component "CreateComponent3"
named bodies: "Wall anchor part", "Base plate with slot", "Screw plate", "Screw hole", "Screw hole (3)", "Screw hole (12)", "Screw plate (2)", "Screw hole (1)", "Screw hole (2)", "Screw hole (4)", "Screw plate (1)", "Screw plate (3)", "Wall anchor part (1)"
